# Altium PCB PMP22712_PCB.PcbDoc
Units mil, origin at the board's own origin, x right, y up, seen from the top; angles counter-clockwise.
Board outline 1309.06 x 1072.84 mil, 4 copper layers (Top Layer, Signal Layer 1, Signal Layer 2, Bottom Layer), stack 36.024 mil thick; 30 components, 23 nets, 81 pads, 8 vias.
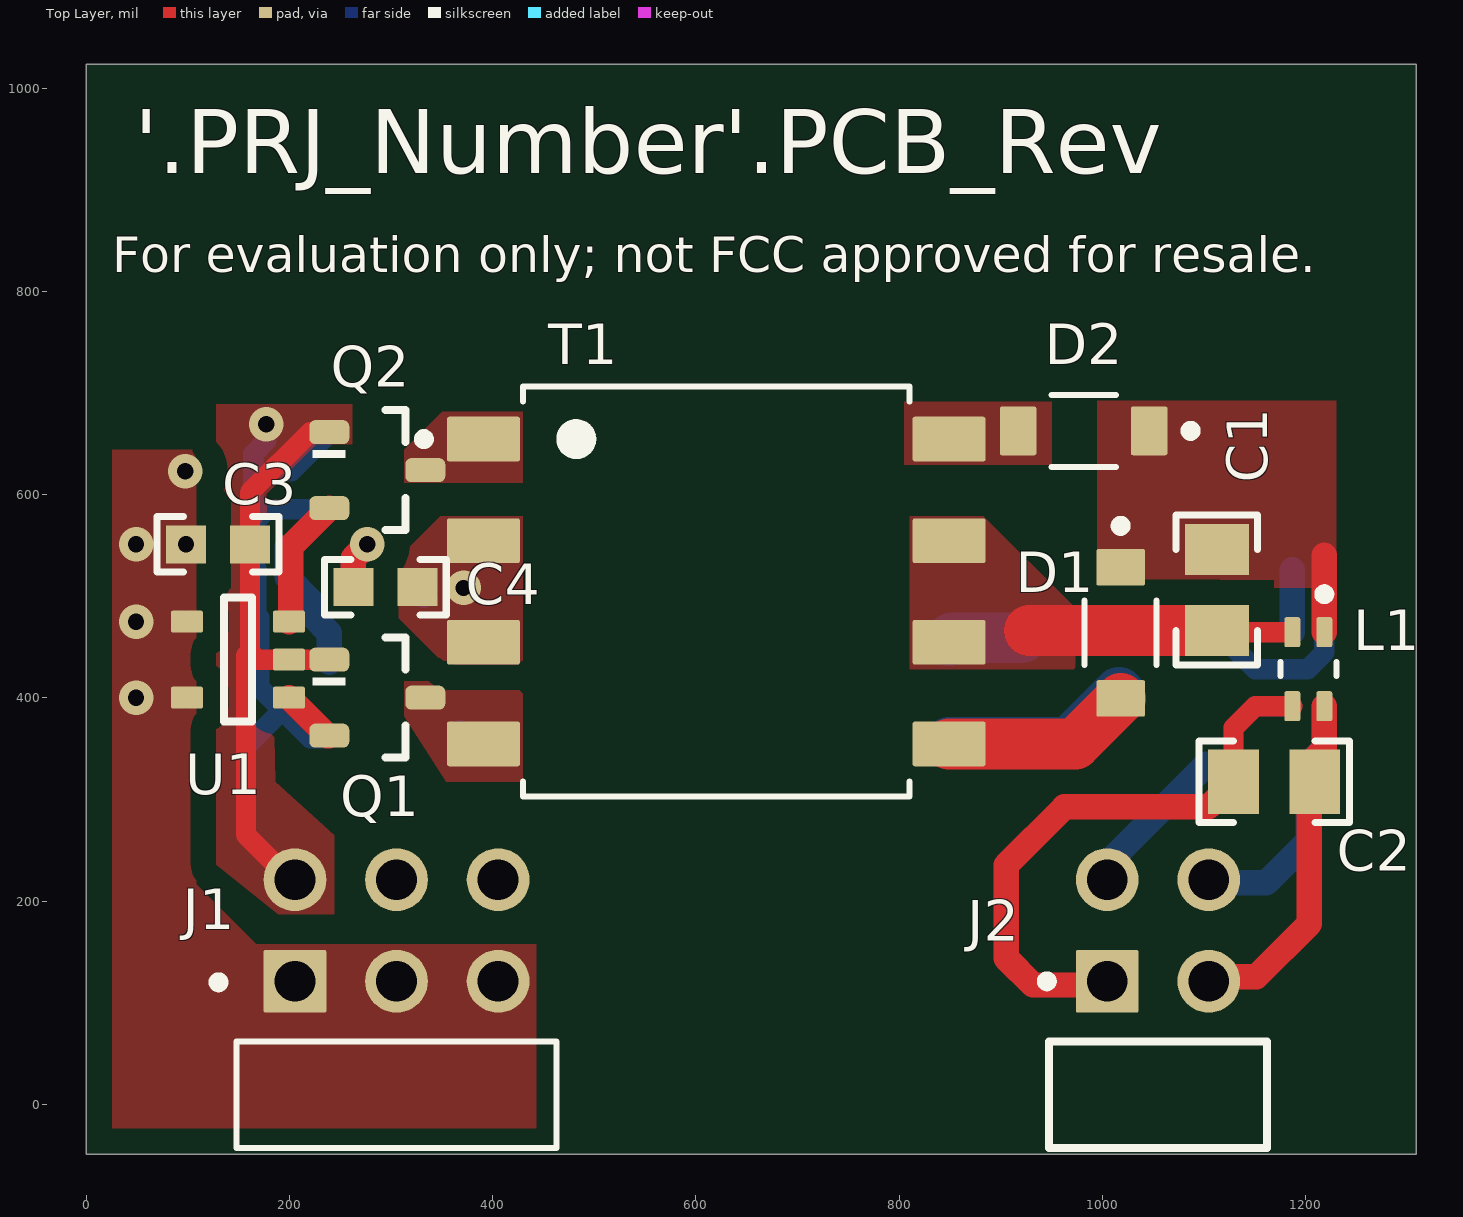
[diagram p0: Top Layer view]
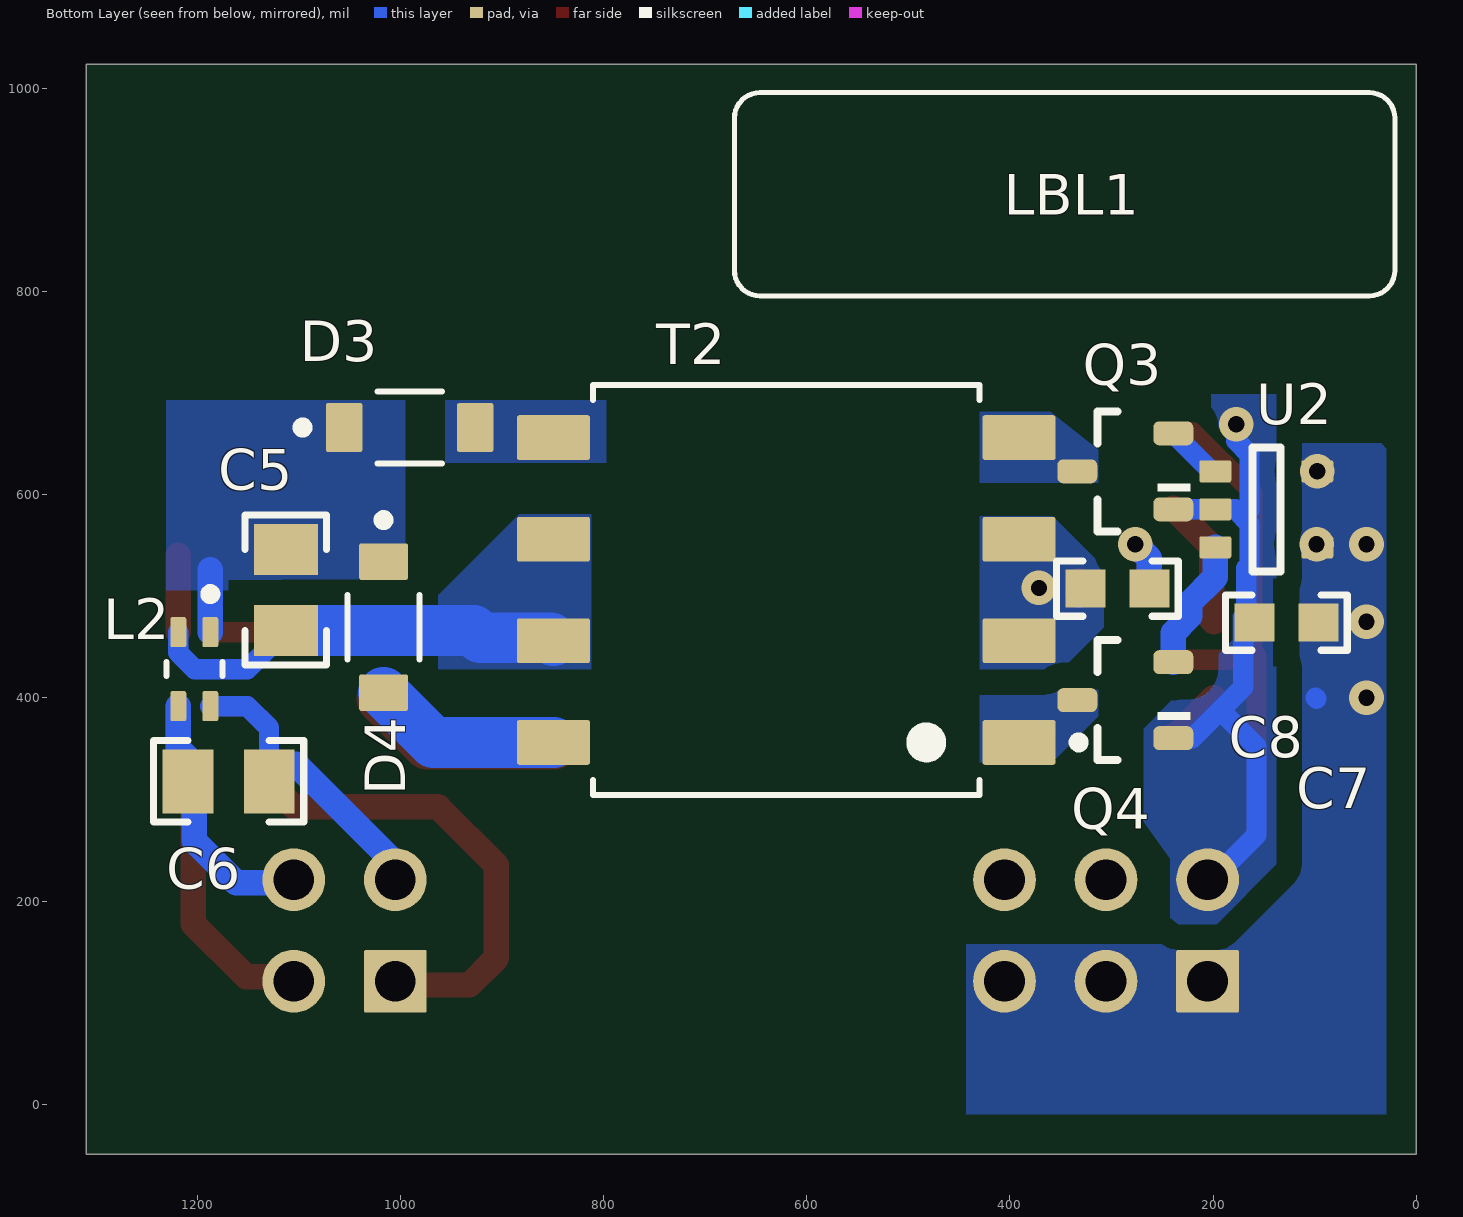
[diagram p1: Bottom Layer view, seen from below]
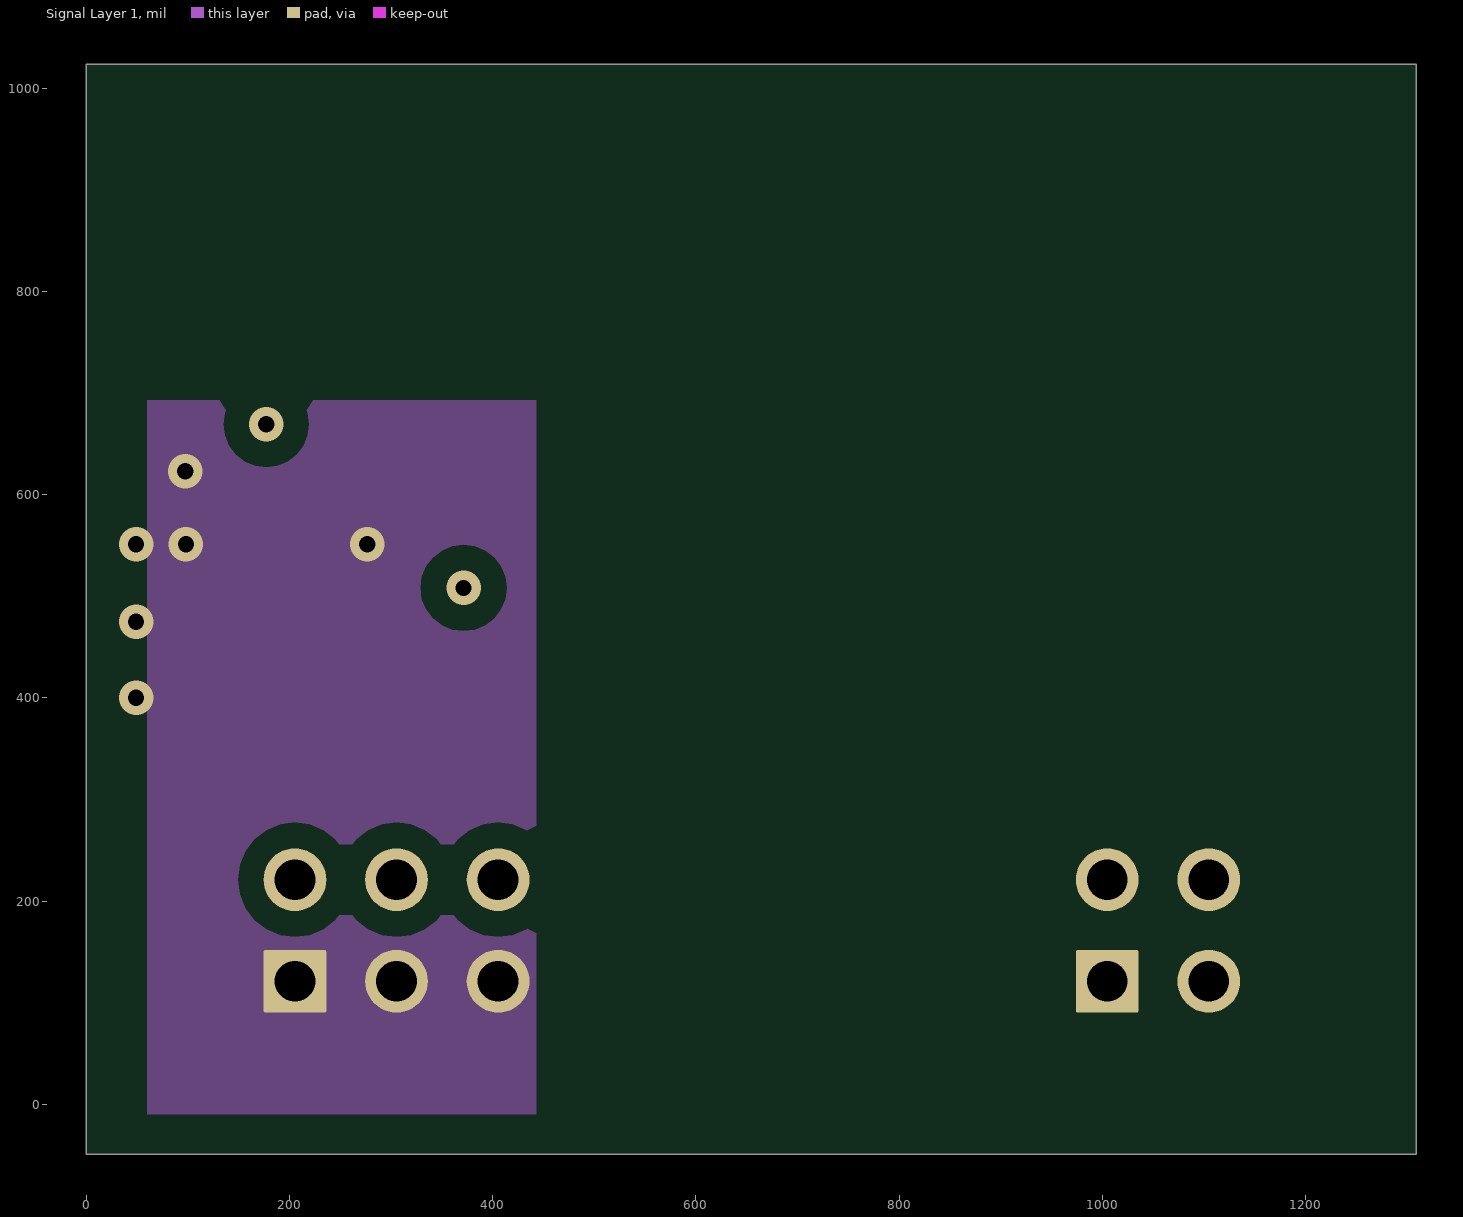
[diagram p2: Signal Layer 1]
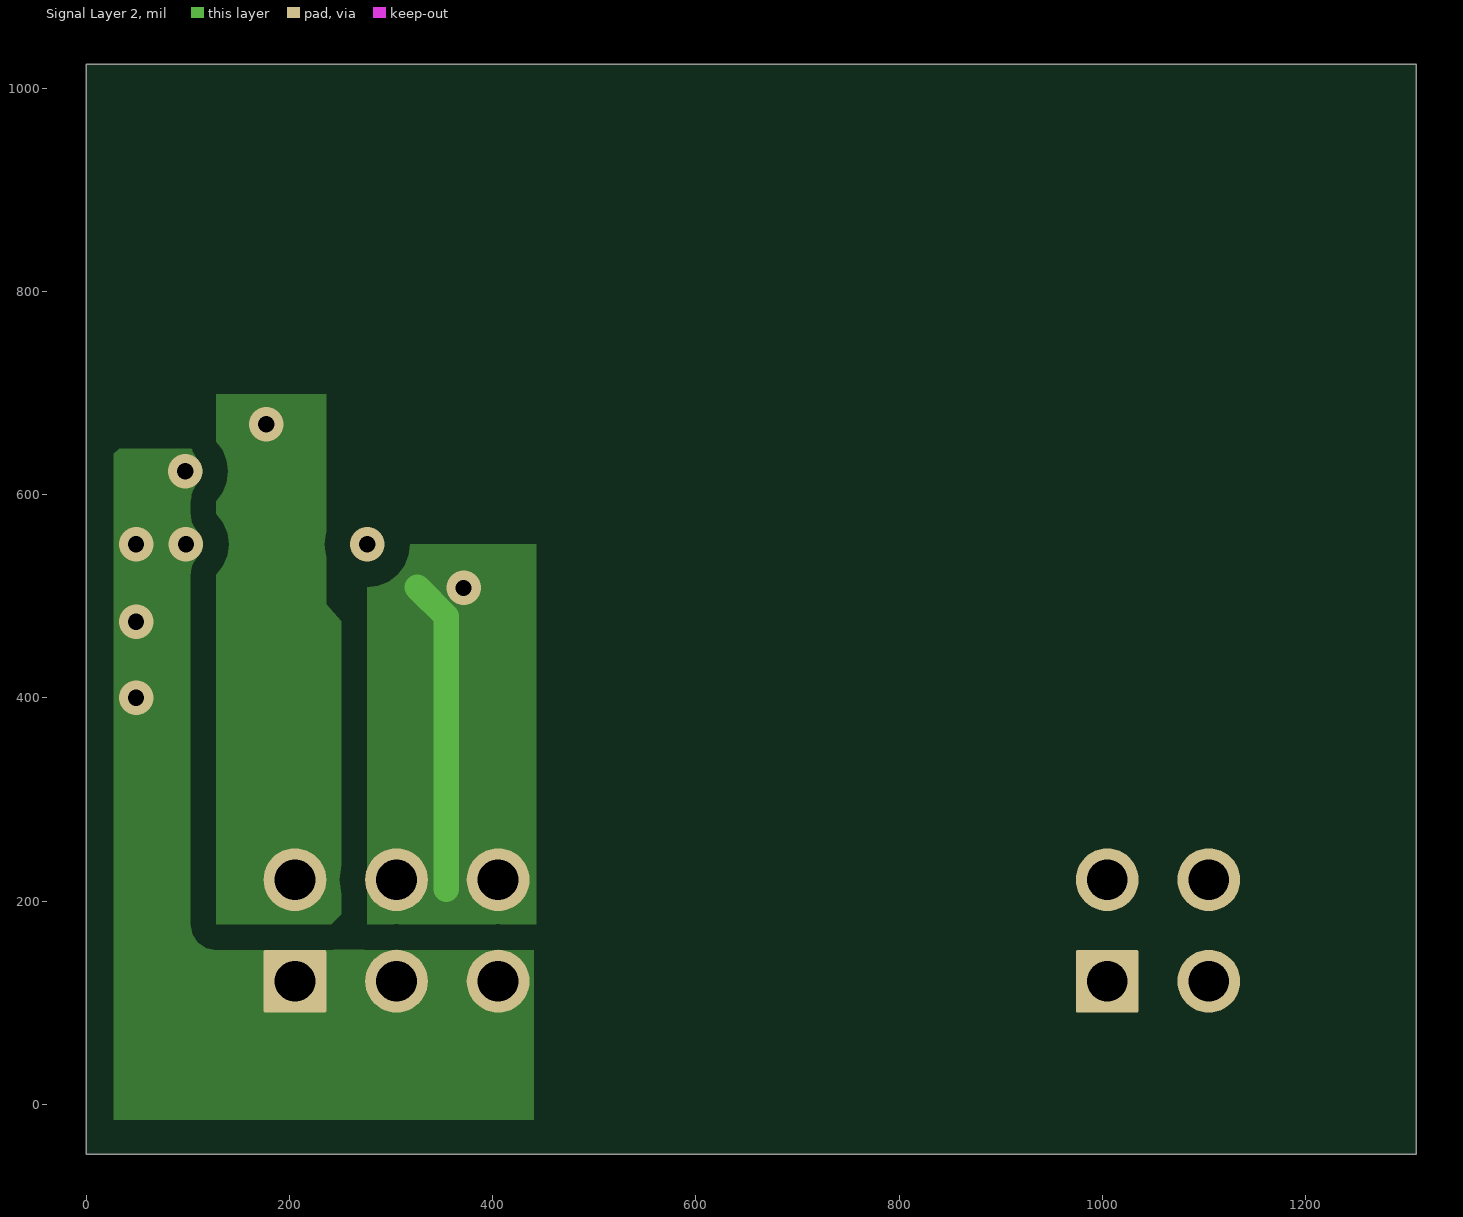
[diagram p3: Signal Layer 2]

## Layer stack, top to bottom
Top Solder: solder mask 0.4, Solder Resist, Dk 3.5
Top Layer: signal copper 2.7559
Dielectric 2: core 10, FR-4, Dk 4.2
Signal Layer 1: signal copper 2.7559
Dielectric1: prepreg 5, FR-4, Dk 4.2
Signal Layer 2: signal copper 2.7559
Dielectric 3: core 10, FR-4, Dk 4.2
Bottom Layer: signal copper 2.7559
Bottom Solder: solder mask 0.4, Solder Resist, Dk 3.5

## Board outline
0,-49.21 1309.06,-49.21 1309.05,1023.62 0,1023.62

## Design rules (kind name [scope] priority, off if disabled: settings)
AcuteAngle [All] p1: minimum=4.50000000000000E+0001 checktracksonly=FALSE
AssemblyTestPointUsage [All] p1: valid=2
BoardOutlineClearance BoardOutlineClearance_MountingHoles [OnCopper and InComponentClass('Mounting Holes')] p1: gap=39.37 ignorepadtopadclearanceinfootprint=FALSE
BoardOutlineClearance BoardOutlineClearance_Poly [OnCopper and IsPoly] p2: gap=25 ignorepadtopadclearanceinfootprint=FALSE
BoardOutlineClearance [OnCopper and Not InComponentClass('Logo') and not InComponentClass('FiducialMark') and not InRegion(1000,500,4000,800) and not InPoly] p3: gap=75 ignorepadtopadclearanceinfootprint=FALSE
Clearance Clearance_Keepouts [((IsTrack Or IsArc) And Not InPoly) And IsFree and IsKeepOut vs ((IsTrack Or IsArc) And Not InPoly) And IsFree and IsKeepOut] p1: gap=0 ignorepadtopadclearanceinfootprint=FALSE
Clearance Clearance_Poly [InPolygon] p2: gap=25 ignorepadtopadclearanceinfootprint=TRUE
Clearance Clearance_FiducialMark [IsKeepOut and InComponentClass('FiducialMark') vs IsPad and InComponentClass('FiducialMark')] p3: gap=0 ignorepadtopadclearanceinfootprint=FALSE
Clearance [All] p4: gap=7.87 ignorepadtopadclearanceinfootprint=TRUE
ComponentClearance ComponentClearance_MountingHoles_FiducialMarks [InComponentClass('Mounting Holes') vs InComponentClass('FiducialMark')] p1: gap=50 collisioncheckmode=3 verticalgap=10 showdistances=FALSE
ComponentClearance ComponentClearance_Shunt [InComponentClass('Header') vs InComponentClass('Shunt')] p2: gap=0 collisioncheckmode=3 verticalgap=0 showdistances=FALSE
ComponentClearance ComponentClearance_Logo [InComponentClass('Logo')] p3: gap=50 collisioncheckmode=3 verticalgap=10 showdistances=FALSE
ComponentClearance ComponentClearance_ScrewToNut [(HasFootprint('NY PMS 440 0025 PH')) vs (HasFootprint('Keystone_1902C'))] p4: gap=5 collisioncheckmode=3 verticalgap=10 showdistances=FALSE
ComponentClearance ComponentClearance_MountingHoles [InComponentClass('Mounting Holes')] p5: gap=250 collisioncheckmode=3 verticalgap=100000 showdistances=FALSE
ComponentClearance ComponentClearance_SmallPassives [HasFootprint('0201*') or HasFootprint('0402*') or HasFootprint('0508') or HasFootprint('0603*') or HasFootprint('0612') or HasFootprint('0805*') or HasFootprint('0815*') or HasFootprint('0830*') or HasFootprint('1206*') or HasFootprint('1210*') or HasFootprint('1808*') or HasFootprint('1812*') or HasFootprint('1825*') or HasFootprint('2010*') or HasFootprint('2220*') or HasFootprint('2225*') or HasFootprint('2512*') or HasFootprint('2728*') or HasFootprint('3518*') vs HasFootprint('0201*') or HasFootprint('0402*') or HasFootprint('0508') or HasFootprint('0603*') or HasFootprint('0612') or HasFootprint('0805*') or HasFootprint('0815*') or HasFootprint('0830*') or HasFootprint('1206*') or HasFootprint('1210*') or HasFootprint('1808*') or HasFootprint('1812*') or HasFootprint('1825*') or HasFootprint('2010*') or HasFootprint('2220*') or HasFootprint('2225*') or HasFootprint('2512*') or HasFootprint('2728*') or HasFootprint('3518*')] p6: gap=14.96 collisioncheckmode=3 verticalgap=10 showdistances=FALSE
ComponentClearance ComponentClearance_THtoSMT [IsThruComponent vs IsSMTComponent] p7: gap=40 collisioncheckmode=3 verticalgap=30 showdistances=FALSE
ComponentClearance ComponentClearance_THtoTH [IsThruComponent vs IsThruComponent] p8: gap=30 collisioncheckmode=3 verticalgap=30 showdistances=FALSE
ComponentClearance [All] p9: gap=30 collisioncheckmode=3 verticalgap=10 showdistances=FALSE
DiffPairsRouting [All] p1: maxlimit=100 minlimit=10 mostfreqgap=10 toplayer_minwidth=15 toplayer_maxwidth=15 toplayer_prefwidth=15 midlayer1_minwidth=15 midlayer1_maxwidth=15 midlayer1_prefwidth=15 midlayer2_minwidth=15 midlayer2_maxwidth=15 midlayer2_prefwidth=15 bottomlayer_minwidth=15 bottomlayer_maxwidth=15 bottomlayer_prefwidth=15 maxuncoupledlength=1000
FabricationTestPointUsage TestPointUsage [All] p1: valid=2 allowmultiple=FALSE
FabricationTestpoint Testpoint [All] p1: side=3 testpointundercomponent=TRUE minsize=40 maxsize=100 preferedsize=60 minholesize=0 maxholesize=40 preferedholesize=32 testpointgrid=1 allowsidetop=TRUE allowsidebottom=TRUE usegrid=TRUE gridtolerance=0.01
FanoutControl Fanout_LCC [IsLCC] p1: bgadir=Out bgaviamode=Centered fanoutstyle=Auto fanoutdirection=Alternating viagrid=1 // Fanout_LCC (Default Rule)
FanoutControl Fanout_BGA [IsBGA] p2: bgadir=Out bgaviamode=Centered fanoutstyle=Auto fanoutdirection=Alternating viagrid=1 // Fanout_BGA (Default Rule)
FanoutControl Fanout_Default [All] p4: bgadir=Out bgaviamode=Centered fanoutstyle=Auto fanoutdirection=Alternating viagrid=1 // Fanout_Default (Default Rule)
FanoutControl Fanout_Small [(CompPinCount < 5)] p5: bgadir=Out bgaviamode=Centered fanoutstyle=Auto fanoutdirection=OutThenIn viagrid=1 // Fanout_Small (Default Rule)
HoleSize [All] p1: absolutevalues=TRUE maxlimit=251 minlimit=7.87 maxpercent=80.000 minpercent=20.000
MinimumAnnularRing MinimumAnnularRing_ThermalPadVias [IsVia and InAnyComponent] p1: minimumring=5.91
MinimumAnnularRing [All] p2: minimumring=7.87
MinimumSolderMaskSliver MinimumSolderMaskSliver_Logo [InComponentClass('Logo') vs InComponentClass('Logo')] p1: minsoldermaskwidth=0.7
MinimumSolderMaskSliver [All] p2: minsoldermaskwidth=3.94
PlaneConnect [All] p1: planeconnectstyle=Direct reliefexpansion=10 reliefentries=4 reliefconductorwidth=10 reliefairgap=10
PolygonConnect [All] p1: connectstyle=Direct reliefconductorwidth=10 reliefentries=4 polygonreliefangle="90 Angle" airgapwidth=10
RoutingVias ThermalPadVias [IsVia and InAnyComponent] p1: holewidth=7.87 width=19.68 viastyle="Through Hole" minholewidth=7.87 minwidth=19.68 maxholewidth=12.99 maxwidth=23.62
RoutingVias [All] p2: holewidth=16 width=34 viastyle="Through Hole" minholewidth=7.87 minwidth=26 maxholewidth=40 maxwidth=65
SilkToBoardRegionClearance [Not ((IsComment or IsDesignator) And (Hide <> 'False')) and not InRegion(1000,500,4000,800)] p1:
SilkToSilkClearance SilkToSilkClearance_Pb-FreeLogo [(HasFootprint('Pb-Free_Overlay_Medium') OR HasFootprint('Pb-Free_Overlay_Small')) vs (HasFootprint('Pb-Free_Overlay_Medium') OR HasFootprint('Pb-Free_Overlay_Small'))] p1: silktosilkclearance=0
SilkToSilkClearance [All] p2: silktosilkclearance=3.94
SilkToSolderMaskClearance SilkToComponentPadClearance [(IsPad or IsFill or IsRegion) and InAnycomponent] p1: minsilkscreentomaskgap=5 clearancetoexposedcopper=TRUE
SilkToSolderMaskClearance "Silk to Solder Mask Opening" [All] p2: minsilkscreentomaskgap=3.94 clearancetoexposedcopper=FALSE
SolderMaskExpansion [All] p1: expansion=1.97 istentingtop=FALSE
UnRoutedNet [All] p1: checkbadconnections=TRUE
Width [All] p1: maxlimit=100 minlimit=6 preferedwidth=10 checkconnectedcopper=TRUE
14 further rules are at their usual default settings.

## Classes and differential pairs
net class VSWNET: H_T4 H_T5 H_T6 H_VOUT HS_GND ISO_12V_H
net class PGND: H_VOUT ISO_12V_L L_T4 L_T5 L_T6 LS_GND
net class INGND: 5V_PRI 12V_PRI H_D1 H_D2 H_FET_D1 H_FET_D2 L_D1 L_D2 L_FET_D1 L_FET_D2 PGND
component class PMP22712_Main: C1 C2 C3 C4 C5 C6 C7 C8 D1 D2 D3 D4 J1 J2 L1 L2 Q1 Q2 Q3 Q4 T1 T2 U1 U2
component class PMP22712_Hardware: LBL1 Logo3 ZZ1 ZZ2 ZZ3 ZZ4
component class AssemblyNote: ZZ1 ZZ2 ZZ3 ZZ4
component class Label: LBL1

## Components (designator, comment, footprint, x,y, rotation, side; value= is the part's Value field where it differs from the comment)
C1 "GRM21BR71E475KA73L" 0805_HV 1112.7,506.17 r270 top value=4.7uF
C2 "GRM21BR71E475KA73L" 0805_HV 1169.2,317.44 r180 top value=4.7uF
C3 "UMK107AB7105KA-T" 0603 129.62,551.17 r180 top value=1uF
C4 "UMK107AB7105KA-T" 0603 294.29,508.9 r180 top value=1uF
C5 "GRM21BR71E475KA73L" 0805_HV 1112.7,506.17 r270 bottom value=4.7uF
C6 "GRM21BR71E475KA73L" 0805_HV 1169.03,317.88 r0 bottom value=4.7uF
C7 "UMK107AB7105KA-T" 0603 127.95,474.09 r180 bottom value=1uF
C8 "UMK107AB7105KA-T" 0603 294.29,507.59 r180 bottom value=1uF
D1 "NRVB0540T1G" FP-NRVB0540T1G_SOD-123-MFG#1 1018.11,463.98 r270 top
D2 "NRVB0540T1G" FP-NRVB0540T1G_SOD-123-MFG#1 981.61,662.8 r180 top
D3 "NRVB0540T1G" FP-NRVB0540T1G_SOD-123-MFG#2 990.82,666.1 r180 bottom
D4 "NRVB0540T1G" FP-NRVB0540T1G_SOD-123-MFG#2 1016.42,469.68 r270 bottom
J1 "TSW-103-08-G-D-RA" FP-TSW-103-08-G-D-RA_HDR6-MFG 305.36,12.01 r0 top
J2 "TSW-102-08-G-D-RA" FP-TSW-102-08-G-D-RA_HDR4-MFG 1054.87,12.01 r0 top
L1 "ACM2012-900-2P-T001" FP-ACM2012-900-2P-T001_SMD4-MFG#1 1202.76,428.2 r270 top
L2 "ACM2012-900-2P-T001" FP-ACM2012-900-2P-T001_SMD4-MFG#2 1202.76,428.32 r270 bottom
LBL1 "THT-14-423-10" Label_650x200 346.08,895.67 r180 bottom
Logo3 "FCC disclaimer" FCC_disclaimer 2372.05,3120.08 r0 top
Q1 "ZXMN10A07FTA" SOT-23 286.42,400.23 r0 top value=100V
Q2 "ZXMN10A07FTA" SOT-23 286.42,624.14 r0 top value=100V
Q3 "ZXMN10A07FTA" SOT-23 286.42,622.93 r0 bottom value=100V
Q4 "ZXMN10A07FTA" SOT-23 286.42,397.77 r0 bottom value=100V
T1 "901-20113-V1-01" FP-901-20113-V1-01_SMT_XFRMR_9MM54_10MM26-MFG 620.08,504.69 r0 top
T2 "901-20113-V1-01" FP-901-20113-V1-01_SMT_XFRMR_9MM54_10MM26-MFG 620.08,506.17 r0 bottom
U1 "SN6501QDBVRQ1" DBV0005A_L 149.3,437.63 r180 top
U2 "SN6501QDBVRQ1" DBV0005A_L 147.64,585.53 r180 bottom
ZZ1 "This Assembly Note is for PCB labels only" AssemblyNoteLabel 185,3938 r0 top
ZZ2 "These assemblies are ESD sensitive, ESD precautions shall be observed." AssemblyNote 185,3829.11 r0 top
ZZ3 "These assemblies must be clean and free from flux and all contaminants. Use of no clean flux is not acceptable." AssemblyNote 185,3740.56 r0 top
ZZ4 "These assemblies must comply with workmanship standards IPC-A-610 Class 2, unless otherwise specified." AssemblyNote 185,3652 r0 top

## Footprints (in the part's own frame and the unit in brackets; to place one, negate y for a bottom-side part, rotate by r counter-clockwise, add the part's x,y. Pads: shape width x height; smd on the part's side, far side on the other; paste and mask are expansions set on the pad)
0603 [mm] "0603 from SM-752 data"
  rect 1x0.95 smd: 1(-0.8,0) 2(0.8,0)
  silkscreen extent -1.52,-0.69 1.52,0.69, body extent -0.87,-0.47 0.87,0.47, height 1
0805_HV [mil] "0805 with 30mil clearance between pads"
  rect 50x63 smd: 1(-40,0) 2(40,0)
  silkscreen extent -74,-40 74,40, body extent -43,-29 43,29, height 57
AssemblyNote [mil] "Assembly Note"
AssemblyNoteLabel [mil] "Assembly Note for PCB Labels"
DBV0005A_L [mm] "SOT23, 5-Leads, Body 2.9x1.6mm, Pitch 0.95mm, Lead Span 2.8mm, IPC High Density"
  rrect18% 0.8x0.55 smd: 1(-1.275,0.95) 2(-1.275,0) 3(-1.275,-0.95) 4(1.275,-0.95) 5(1.275,0.95)
  silkscreen extent -0.35,-1.55 0.35,1.55, body extent -1.42,-1.46 1.42,1.46, height 1.09
FCC_disclaimer [mil]
FP-901-20113-V1-01_SMT_XFRMR_9MM54_10MM26-MFG [mm]
  rrect9% 1.82x1.12 smd paste+0 mask+0: 1(-5.82,3.81) 2(-5.82,1.27) 3(-5.82,-1.27) 4(-5.82,-3.81) 5(5.82,-3.81) 6(5.82,-1.27) 7(5.82,1.27) 8(5.82,3.81)
  silkscreen extent -7.43,-5.13 4.83,5.13, body extent -6.83,-5.23 6.83,5.23, height 0.25
FP-ACM2012-900-2P-T001_SMD4-MFG#1 [mm]
  rrect25% 0.75x0.4 smd: 1(-0.925,0.4) 2(-0.925,-0.4) 3(0.925,-0.4) 4(0.925,0.4)
  silkscreen extent -2,-0.7 0.18,0.7, body extent -1.4,-0.8 1.4,0.8, height 0.25
FP-ACM2012-900-2P-T001_SMD4-MFG#2 [mm]
  rrect25% 0.75x0.4 smd paste+0 mask+0: 1(-0.925,0.4) 2(-0.925,-0.4) 3(0.925,-0.4) 4(0.925,0.4)
  silkscreen extent -2,-0.7 0.18,0.7, body extent -1,-0.6 1,0.6, height 1.3
FP-NRVB0540T1G_SOD-123-MFG#1 [mil]
  rrect11% 36x48 smd: 1(-64.5,0) 2(64.5,0)
  silkscreen extent -110,-35 32,35, body extent -86,-39 86,39, height 10
FP-NRVB0540T1G_SOD-123-MFG#2 [mil]
  rrect11% 36x48 smd paste+0 mask+0: 1(-64.5,0) 2(64.5,0)
  silkscreen extent -110,-35 32,35, body extent -72,-31 72,31, height 53
FP-TSW-102-08-G-D-RA_HDR4-MFG [mm]
  rrect6% 1.57x1.57 hole 1.02 paste-1000 mask+0: 1(-1.27,2.77)
  round 1.57 hole 1.02 paste-1000 mask+0: 2(-1.27,5.31) 3(1.27,2.77) 4(1.27,5.31)
  silkscreen extent -2.9,-1.4 2.73,2.89, body extent -2.83,-7.54 2.83,6.2, height 0.25
FP-TSW-103-08-G-D-RA_HDR6-MFG [mm]
  rrect6% 1.57x1.57 hole 1.02 paste-1000 mask+0: 1(-2.54,2.77)
  round 1.57 hole 1.02 paste-1000 mask+0: 2(-2.54,5.31) 3(0,2.77) 4(0,5.31) 5(2.54,2.77) 6(2.54,5.31)
  silkscreen extent -4.57,-1.4 4,2.87, body extent -4.1,-7.54 4.1,6.19, height 0.25
Label_650x200 [mil] "Thermal Transfer Label"
  round 1 on Mech14: 0(0,0)
  silkscreen extent -325,-100 325,100, body extent -325,-100 325,100, height 1
SOT-23 [mm] "SOT23, 3-Leads, Body 2.9x1.3mm, Pitch 0.95mm, Lead Span 2.5mm, IPC Medium Density"
  rrect50% 1x0.6 smd: 1(-1.2,0.95) 2(-1.2,-0.95) 3(1.2,0)
  silkscreen extent -1.63,-1.5 0.7,1.5, body extent -1.16,-1.45 1.21,1.45, height 1

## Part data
C1 C2 C5 C6: library part CMP-0008346-2, "CAP, CERM, 4.7 uF, 25 V, +/- 10%, X7R, 0805", Cap_Case=0805, Manufacturer=MuRata, Supplier Part Number 1=490-9962-1-ND, TempCo=X7R, Tolerance_%=10%, Value1=Unknown, Value2=25V, ValueDisplayed=4.7uF
C3 C4 C7 C8: library part CMP-0007508-5, "CAP, CERM, 1 uF, 50 V, +/- 10%, X7R, 0603", Cap_Case=0603, Manufacturer="Taiyo Yuden", Supplier Part Number 1=587-3247-1-ND, TempCo=X7R, Tolerance_%=10%, Value1=Unknown, Value2=50V, ValueDisplayed=1uF
D1 D2 D3 D4: library part CMP-0090564-1, "Diode Schottky 40V 500mA Surface Mount SOD-123", Digikey Part Number=NRVB0540T1GOSCT-ND, Forward Current=0.5A, Manufacturer="On Semiconductor", Max Surge Forward Current=5.5A, Mouser Part Number=863-NRVB0540T1G, Operating Temperature Range="-55°C to +150°C", Peak Reverse Current=20uA
J1: library part CMP-0090622-1, "Connector Header Through Hole, Right Angle 6 position 0.100\" (2.54mm)", Current_A=5.7A, Digikey Part Number=SAM1037-03-ND, Manufacturer=Samtec, Mouser Part Number=200-TSW10308GDRA, Operating Temperature Range="-55°C to +125°C", Voltage_V=550V
J2: library part CMP-0088304-1, "CONN HEADER R/A 4POS 2.54MM", Digikey Part Number=SAM1037-02-ND, Manufacturer=Samtec, Mouser Part Number=200-TSW10208GDRA, Operating Temperature Range="-55°C to +125°C"
L1 L2: library part CMP-0090488-1, "2 Line Common Mode Choke Surface Mount 90 Ohms @ 100MHz 400mA DCR 190mOhm", Digikey Part Number=445-15969-1-ND, Impedance At Frequency="90Ω @ 100MHz", Manufacturer=TDK, Mouser Part Number=810-ACM20129002PT001, Operating Temperature Range="-40°C to +105°C"
LBL1: library part CMP-0003625-1, "Thermal Transfer Printable Labels, 0.650\" W x 0.200\" H - 10,000 per roll", Manufacturer=Brady, Supplier Part Number 1=97C5133
Logo3: library part CMP-0074847-1, "FCC_disclaimer"
Q1 Q2 Q3 Q4: library part CMP-0001041-3, "MOSFET, N-CH, 100 V, 0.7 A, AEC-Q101, SOT-23", Alternate Manufacturer=None, Manufacturer="Diodes Inc.", Supplier Part Number 1=ZXMN10A07FCT-ND, Value2="2.9 nC"
T1 T2: library part CMP-0090597-1, "Automotive Transformer, 1:1, 80uH, 3500VAC, SMT, 9.54x10.26x5.38", Frequency_Fixed=300-620kHz, Manufacturer="Wurth Electronics", Operating Temperature Range="-40°C to +125°C", Voltage_Isolation_Vrms=3.5kV
U1 U2: library part CMP-0076093-1, "Automotive Low-Noise 350 mA, 410 kHz Transformer Driver, DBV0005A (SOT-23-5)", Alternate Manufacturer="Texas Instruments"
ZZ1: library part CMP-0003616-3
ZZ2: library part CMP-0077236-1
ZZ3: library part CMP-0077237-1
ZZ4: library part CMP-0077238-1

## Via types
v1: diameter 34, hole 16, Top Layer to Bottom Layer, 8 vias

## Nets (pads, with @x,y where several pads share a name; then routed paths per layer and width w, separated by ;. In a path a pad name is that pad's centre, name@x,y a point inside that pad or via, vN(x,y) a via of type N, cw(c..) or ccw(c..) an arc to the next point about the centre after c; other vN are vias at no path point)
5V_PRI: C3.1 C7.1 J1.2 Q1.1 Q2.1 Q3.1 Q4.1 U1.2 U2.2 | length 1230.9
  Top Layer w20: J1.2@204.43,217.81 157.29,264.96 157.29,441.68 161.11,445.5 ; Q1.1 U1.2 168.99,437.63 161.11,445.5 ; Q2.1 220.49,661.55 161.11,602.17 C3.1 161.11,445.5
  Bottom Layer w20: v1(177.17,669.29) 177.17,652.97 164.21,640.02 164.21,584.55 177.17,584.55 ; J1.2@204.43,217.81 157.29,264.96 157.29,352.5 192.71,387.92 ; Q4.1 220.27,360.36 192.71,387.92 ; Q3.1 U2.2 178.15,585.53 177.17,584.55 ; 177.17,584.55 164.21,571.59 164.21,531.04 167.46,527.79 167.46,481.86 170.28,479.05 170.28,410.36 192.71,387.92
12V_PRI: C4.1 C8.1 J1.4 J1.6 T1.2 T1.3 T2.2 T2.3 | length 397.3
  Top Layer w25: C4.1@331.99,515.1 C4.1 326.77,508.9 C4.1@332.97,502.7 ; T1.3@377.17,454.69 T1.3 ; T1.2@377.17,554.69 T1.2
  Signal Layer 2 w25: 325.79,508.9 354.43,480.25 354.43,211.68
  Bottom Layer w25: C8.1@329.89,508.9 325.79,508.9 332.26,502.42 C8.1@332.26,501.07 ; T2.2@377.17,456.17 T2.2 ; T2.3@377.17,556.17 T2.3
  other v1: 371.36,508.18
H_D1: Q1.2 U1.1 | length 55.2
  Top Layer w25: U1.1 236.9,362.83 Q1.2
H_D2: Q2.2 U1.3 | length 128.1
  Top Layer w25: U1.3 201.17,476.7 201.17,548.74 Q2.2
H_FET_D1: Q1.3 T1.4 | length 13.8
  Top Layer w25: T1.4@377.17,354.69 T1.4
H_FET_D2: Q2.3 T1.1 | length 13.8
  Top Layer w25: T1.1@377.17,654.69 T1.1
H_T4: D1.2 T1.5 | length 188.9
  Top Layer w25: T1.5 T1.5@850.26,355.74
  Top Layer w50: T1.5 973.32,354.69 D1.2
H_T5: C1.2 L1.2 T1.6 T1.7 | length 251.5
  Top Layer w20: C1.2 1114.25,464.62 1179,464.62
  Top Layer w50: 928.19,466.17 C1.2
H_T6: D2.2 T1.8
H_VOUT: C1.1 D1.1 D2.1 L1.1 | length 75.8
  Top Layer w25: L1.1 1218.5,540.38
HS_GND: C2.2 J2.1 L1.3 | length 578.5
  Top Layer w20: C2.2 1129.2,370.61 1150.37,391.78 L1.3
  Top Layer w25: J2.1@1003.94,117.39 931.83,117.39 905.51,143.72 905.51,235.5 962.73,292.72 1104.47,292.72 C2.2
ISO_12V_H: C2.1 J2.3 L1.4 | length 342.4
  Top Layer w25: J2.3@1103.94,125.66 1151.82,125.66 1203.74,177.58 1203.74,332.94 1202.76,333.93 1218.5,349.68 L1.4
ISO_12V_L: C6.1 J2.2 L2.4 | length 301.8
  Bottom Layer w20: C6.1@1139.76,334.5 1129.2,345.07 1129.2,370.61 1150.37,391.78 1186.88,391.78 L2.4
  Bottom Layer w25: J2.2@1003.94,217.97 1003.94,236.08 1102.36,334.5 C6.1@1139.76,334.5
L_D1: Q3.2 U2.1 | length 56.8
  Bottom Layer w20: U2.1 201.77,622.93 Q3.2
L_D2: Q4.2 U2.3 | length 130.1
  Bottom Layer w25: U2.3 197.83,518.69 222.74,493.78 222.74,480.45 239.17,464.01 Q4.2
L_FET_D1: Q3.3 T2.4 | length 13.8
  Bottom Layer w25: T2.4@377.17,656.17 T2.4
L_FET_D2: Q4.3 T2.1 | length 27.3
  Bottom Layer w25: T2.1@367.62,365.72 377.17,356.17 T2.1
L_T4: D3.2 T2.5
L_T5: C5.2 L2.2 T2.6 T2.7 | length 416
  Bottom Layer w20: C5.2 1150.54,428.32 1202.19,428.32 1218.5,444.64 L2.2
  Bottom Layer w50: T2.7 852.17,459.12 921.14,459.12 928.19,466.17 C5.2
L_T6: D4.2 T2.8 | length 187.5
  Bottom Layer w50: T2.8 967.41,356.17 D4.2
L_VOUT: C5.1 D3.1 D4.1 L2.1 | length 61.6
  Bottom Layer w25: 1186.88,526.27 1187.01,526.14 L2.1
LS_GND: C6.2 J2.4 L2.3 | length 255.1
  Bottom Layer w25: J2.4@1103.94,217.97 1161.42,217.97 1202.76,259.31 1202.76,334.5 1218.5,350.25 L2.3
PGND: C3.2 C4.2 C7.2 C8.2 J1.1 J1.3 J1.5 U1.4 U1.5 U2.4 U2.5 | length 100.1
  Top Layer w20: U1.4@98.12,476.01 U1.4
  Top Layer w25: C4.2 262.8,537.39 v1(276.57,551.17)
  Bottom Layer w20: 98.12,399.24 99.11,400.23
  Bottom Layer w25: C8.2 262.8,537.39 v1(276.57,551.17)
  other v1: 49,400.23 49,475.03 49,551.17 98.12,551.17 97.44,622.93
pads on no net: LBL1.0

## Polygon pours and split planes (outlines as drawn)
H_T5 on Top Layer "TOP_LAYER_H_T5_P030" (solid, pour order 30): 810.43,578.91 810.43,428.32 973.32,428.32 973.32,488.66 883.07,578.91
H_FET_D2 on Top Layer "TOP_LAYER_H_FET_D2_P029" (solid, pour order 29): 429.72,681.59 350.46,681.59 312.99,644.12 312.99,611.97 429.72,611.97
12V_PRI on Top Layer "TOP_LAYER_12V_PRI_P028" (solid, pour order 28): 429.72,578.91 348.56,578.91 305.12,535.47 305.12,480.84 357.76,428.2 429.72,428.2
H_T6 on Top Layer "TOP_LAYER_H_T6_P027" (solid, remove dead copper, pour order 27): 805.16,691.37 805.16,629.48 950.44,629.48 950.44,691.37
H_FET_D1 on Top Layer "TOP_LAYER_H_FET_D1_P025" (solid, pour order 25): 429.72,317.44 429.72,416.14 312.99,416.14 312.99,381.67 354.43,317.44
H_VOUT on Top Layer "TOP_LAYER_L_VOUT_P000" (solid, remove dead copper, pour order 0): 995.08,692.32 995.08,508.18 1230.31,508.18 1230.31,692.32
PGND on Top Layer "TOP_LAYER_PGND_P018" (solid, remove dead copper, pour order 18): 442.91,157.48 167.32,157.48 108.27,216.54 108.27,644.11 19.68,644.11 19.68,-29.53 442.91,-29.53
5V_PRI on Top Layer "TOP_LAYER_5V_PRI_P016" (solid, remove dead copper, pour order 16): 127.95,688.98 127.95,235.79 188.93,187.01 244.26,187.01 244.26,264.94 186.19,317.44 177.17,600.39 226.38,649.61 261.81,649.61 261.81,688.98
PGND on Signal Layer 2 "SIGNAL_LAYER_2_PGND_P032" (solid, remove dead copper, pour order 32): 440.6,152.3 184.69,152.3 115.8,221.2 115.8,645.31 32.3,645.31 27.21,640.22 27.21,-15.02 440.6,-15.02
5V_PRI on Signal Layer 2 "SIGNAL_LAYER_2_5V_PRI_P014" (solid, remove dead copper, pour order 14): 285.43,177.17 285.43,241.36 261.81,252.64 261.81,463.22 236.22,492.13 236.22,698.82 127.95,698.82 127.95,177.17
12V_PRI on Signal Layer 2 "SIGNAL_LAYER_2_12V_PRI_P006" (solid, remove dead copper, pour order 6): 276.57,551.17 442.91,551.17 442.91,177.17 276.57,177.17 276.57,338.71
L_FET_D2 on Bottom Layer "BOTTOM_LAYER_L_FET_D2_P031" (solid, pour order 31): 429.72,408.12 312.99,408.12 312.99,381.67 358.19,336.47 429.72,336.47
L_T5 on Bottom Layer "BOTTOM_LAYER_L_T5_P026" (solid, pour order 26): 962.73,428.32 812.14,428.32 812.14,580.62 883.07,580.62 962.73,500.96
12V_PRI on Bottom Layer "BOTTOM_LAYER_12V_PRI_P023" (solid, pour order 23): 429.72,428.2 348.56,428.2 305.12,471.64 305.12,526.27 357.76,578.91 429.72,578.91
L_FET_D1 on Bottom Layer "BOTTOM_LAYER_L_FET_D1_P024" (solid, pour order 24): 429.72,611.97 312.99,611.97 312.99,644.12 360.1,681.59 429.72,681.59
L_T4 on Bottom Layer "BOTTOM_LAYER_L_T4_P010" (solid, remove dead copper, pour order 10): 797.24,692.9 955.71,692.9 955.71,631.32 797.24,631.32
PGND on Bottom Layer "BOTTOM_LAYER_PGND_P022" (solid, remove dead copper, pour order 22): 442.91,157.48 187.01,157.48 118.11,226.38 118.11,650.49 34.62,650.49 29.53,645.4 29.53,-9.84 442.91,-9.84
5V_PRI on Bottom Layer "BOTTOM_LAYER_5V_PRI_P020" (solid, remove dead copper, pour order 20): 242.13,177.17 196.66,177.17 137.8,236.03 137.8,698.82 201.77,698.82 201.77,664.37 177.17,639.76 180.83,636.1 180.83,457.36 268.46,369.73 268.46,278.28 242.13,241.88
L_VOUT on Bottom Layer "BOTTOM_LAYER_H_VOUT_P012" (solid, remove dead copper, pour order 12): 995.08,692.9 995.08,506.17 1230.32,506.17 1230.32,692.9
PGND on Signal Layer 1 "SIGNAL_LAYER_1_PGND_P004" (solid, remove dead copper, pour order 4): 60.04,693.04 442.91,693.04 442.91,-9.84 60.04,-9.84

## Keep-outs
Keep-Out Layer:
  text ".Layer_Name" at 577,-858.49 h60

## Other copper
Top Layer:
  text ".Layer_Name" at 577,-858.49 h60
Bottom Layer:
  text ".Layer_Name" at 577,-858.49 h60

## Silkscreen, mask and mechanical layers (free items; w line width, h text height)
Top Overlay:
  text "'.PRJ_Number'.PCB_Rev" at 47.1,895.67 h108.27
  text ".Layer_Name" at 577,-858.49 h60
Bottom Overlay:
  text ".Layer_Name" at 577,-858.49 h60
Top Paste:
  text ".Layer_Name" at 577,-858.49 h60
Bottom Paste:
  text ".Layer_Name" at 577,-858.49 h60
Top Solder:
  text ".Layer_Name" at 577,-858.49 h60
  text ".Layer_Name" at 577,-858.49 h60
Bottom Solder:
  text ".Layer_Name" at 577,-858.49 h60
Drill Guide:
  text ".Layer_Name" at 577,-858.49 h60
M1 Board Outline:
  the board outline again, w10
  text ".Layer_Name" at 577,-858.49 h60
M2 Board Dimensions:
  rectangle: 0,-275 125,-150
  rectangle: 125,-400 500,-275
  lines w7: 0,-275 1000,-275 ; 125,-400 125,-150 ; 250,-400 250,-150 ; 500,-400 500,-150 ; 750,-400 750,-150 ; 0,-400 1000,-400 1000,-150 0,-150 0,-400
  text ".Layer_Name" at 577,-858.49 h60
M3 3D STEP Top:
  text ".Layer_Name" at 577,-858.49 h60
M4 3D STEP Bottom:
  text ".Layer_Name" at 577,-858.49 h60
M5 Assembly Top:
  lines w10: -292,-930.17 6308,-930.17 ; -292,-726.83 6310,-726.83 ; -292,-523.5 -292,-1133.5 3713,-1133.5 6310,-1133.5 6310,-523.5 -291.5,-523.5 -291.5,-1133.5 1284,-1133.5 ; 2173,-1133.5 2173,-523.5 ; 3440,-726.83 3440,-523.5 ; 4280,-726.83 4280,-523.5 ; 4902,-1140 4902,-937.17
  text "COMPONENTS MARKED 'DNP' SHOULD NOT BE POPULATED." at 1153.5,-318.5 h60
  text "ASSEMBLY VARIANT:" at 1153,-434 h60
  text ".VariantName" at 2189,-434 h60
  text "PCB VIEWED FROM TOP SIDE" at -228.5,-655.67 h60
  text "BOARD #:" at 2248,-655.67 h60
  text ".PRJ_Number" at 2793.5,-655.67 h60
  text "REV:" at 3638,-655.67 h60
  text ".PCB_Rev" at 3929.5,-655.67 h60
  text "SVN REV:" at 4476,-655.67 h60
  text ".VersionControl_RevNumber" at 4982,-655.67 h60
  text "TID #:" at 2248,-859 h60
  text ".TID" at 2793.5,-859 h60
  text "PLOT NAME =" at -228.5,-1064.34 h60
  text ".plot_File_Name" at 577,-1064.34 h60
  text "GENERATED    :" at 2250,-1064.34 h60
  text ".Print_Date" at 3119.5,-1064.34 h60
  text ".Print_Time" at 3848.5,-1064.34 h60
  text "TEXAS INSTRUMENTS" at 5113,-1064.34 h60
M6 Assembly Bottom:
  lines w10: -292.5,-727.33 6309.5,-727.33 ; -290.5,-930.67 6309.5,-930.67 ; 1115.5,-1140.5 1115.5,-937.67 ; 1737.5,-727.33 1737.5,-524 ; 2577.5,-727.33 2577.5,-524 ; 3844.5,-1134 3844.5,-524 ; 4733.5,-1134 6309,-1134 6309,-524 -292.5,-524 -292.5,-1134 2304.5,-1134 6309.5,-1134 6309.5,-524
  text "COMPONENTS MARKED 'DNP' SHOULD NOT BE POPULATED." at 6102,-318 h60
  text ".VariantName" at 5058,-434 h60
  text "ASSEMBLY VARIANT:" at 6097,-434 h60
  text ".VersionControl_RevNumber" at 1035.5,-656.17 h60
  text "SVN REV:" at 1541.5,-656.17 h60
  text ".PCB_Rev" at 2088,-656.17 h60
  text "REV:" at 2379.5,-656.17 h60
  text ".PRJ_Number" at 3224,-656.17 h60
  text "BOARD #:" at 3769.5,-656.17 h60
  text "PCB VIEWED FROM BOTTOM SIDE" at 6246,-656.17 h60
  text ".TID" at 3224,-859.5 h60
  text "TID #:" at 3769.5,-859.5 h60
  text "TEXAS INSTRUMENTS" at 904.5,-1064.84 h60
  text ".Print_Time" at 2169,-1064.84 h60
  text ".Print_Date" at 2898,-1064.84 h60
  text "GENERATED    :" at 3767.5,-1064.84 h60
  text ".plot_File_Name" at 5440.5,-1064.84 h60
  text "PLOT NAME =" at 6246,-1064.84 h60
M9 Title Sheet:
  drawing of 57 lines, arcs and shapes, not listed
  text "1" at 739.84,8036.5 h70
  text "2" at 3235.5,8036.5 h70
  text "3" at 5724.84,8036.5 h70
  text "4" at 8231.51,8036.5 h70
  text "5" at 10730.5,8036.5 h70
  text "6" at 13235.5,8036.5 h70
  text "A" at -416.5,6893.5 h70
  text "A" at 14383.5,6893.5 h70
  text "B" at -416.5,4513.5 h70
  text "B" at 14383.5,4513.5 h70
  text "C" at -416.5,2138.5 h70
  text "C" at 14383.5,2138.5 h70
  text "PROJECT TITLE:" at 11343.5,277.5 h45
  text ".PRJ_Title" at 11393.5,144.17 h70
  text "DESIGNED FOR:" at 11343.5,-23.5 h45
  text ".PRJ_Customer" at 11393.5,-163.5 h70
  text "D" at -416.5,-231.5 h70
  text "D" at 14383.5,-231.5 h70
  text "FILE NAME:" at 11343.5,-323.5 h45
  text ".PCB_File_Name_No_Path" at 11393.5,-443.5 h70
  text "Texas Instruments (TI) and/or its licensors do not warrant the accuracy or completeness of this specification" at 6374,-605.34 h45
  text "ENGINEER:" at 11343.5,-613.5 h45
  text "LAYOUT BY:" at 12848.5,-613.5 h45
  text "or any information contained therein. TI and/or its licensors do not warrant that this design will meet" at 6329.01,-718 h45
  text ".PRJ_Engineer" at 11393.5,-768.49 h70
  text ".PCB_Layout" at 12899,-768.49 h70
  text "the specifications, will be suitable for your application or fit for any particular purpose, or will operate in" at 6329.01,-830.67 h45
  text ".Layer_Name" at 577,-858.49 h60
  text "ALTIUM DESIGNER VERSION:" at 12848.5,-923.5 h45
  text "an implementation. TI and/or its licensors do not warrant that the design is production worthy. You should" at 6329.01,-943.33 h45
  text "completely validate and test your design implementation to confirm the system functionality for your application." at 6374,-1056 h45
  text ".print_Scale" at 11393.5,-1056.83 h70
  text ".Application_BuildNumber" at 12899,-1056.83 h70
  text "1" at 739.84,-1263.5 h70
  text "2" at 3235.5,-1263.5 h70
  text "3" at 5724.84,-1263.5 h70
  text "4" at 8231.51,-1263.5 h70
  text "5" at 10730.5,-1263.5 h70
  text "6" at 13235.5,-1263.5 h70
M10 Fab Notes:
  drawing of 189 lines, arcs and shapes, not listed
  text "DESIGN INFORMATION" at 12382.02,6356.17 h60
  text "MIN. TRACK WIDTH:" at 11737.46,6224.05 h60
  text "8" at 12833.7,6224.05 h60
  text "MIL" at 12988.46,6224.05 h60
  text "MIN. CLEARANCE:" at 11737.46,6099.92 h60
  text "0.2" at 12773.7,6099.93 h60
  text "mm" at 12988.46,6099.92 h60
  text "MIN. VIA PAD SIZE:" at 11737.46,5975.8 h60
  text "24" at 12803.71,5975.8 h60
  text "MIL" at 12988.46,5975.8 h60
  text "0.05mm (2MIL)" at 12432.46,5845.9 h60
  text "MINIMUM ANNULAR RING" at 11408.23,5837.67 h60
  text "EXTERNAL" at 13140.46,5837.67 h60
  text "PER" at 11608.23,5727.55 h60
  text "IPC-D-275 CLASS 2 LEVEL C" at 11828.23,5727.54 h60
  text "MIL, HOLES" at 13316.46,5627.07 h60
  text "+/-" at 12924,5618.48 h60
  text "+/-" at 13778,5618.48 h60
  text "REGISTRATION TOLERANCES:" at 11408.23,5617.42 h60
  text "METAL" at 12608,5617.42 h60
  text "5" at 13184.2,5617.42 h60
  text "3" at 14017.2,5617.42 h60
  text "MIL" at 14133.46,5617.42 h60
  text "HOLE SIZE TOLERANCE (UNLESS OTHERWISE SPECIFIED):" at 11408.23,5519.1 h60
  text "+/-" at 13778,5516.23 h60
  text "3" at 14017.2,5515.17 h60
  text "MIL" at 14133.46,5515.17 h60
  text "MATERIAL:" at 11333.46,5377.52 h60
  text "FR-4 High Tg" at 12319.9,5249 h60
  text "X" at 12175.46,5241.01 h60
  text "FR-408" at 11754.46,5236.49 h60
  text "OTHER" at 13242.46,5236.49 h60
  text "62 MIL (1.6mm) +/-10%" at 12074.56,5093.46 h60
  text "X" at 11954.46,5091.01 h60
  text "THICKNESS:" at 11408.23,5085.24 h60
  text "OTHER" at 13359.46,5085.24 h60
  text "TOLERANCE:" at 11408.23,4946.92 h60
  text "X" at 12256.46,4946.92 h60
  text "ANSI IPC-6012 TYPE 3 CLASS 2" at 12434.48,4946.92 h60
  text "OTHER +/-" at 12434.46,4802.73 h60
  text "BOW & TWIST:" at 11408.23,4657.54 h60
  text "X" at 12256.46,4657.54 h60
  text "ANSI IPC-6012 TYPE 3 CLASS 2" at 12434.48,4657.54 h60
  text "OTHER +/-" at 12434.46,4510.85 h60
  text "DRILLING:" at 11333.46,4380.23 h60
  text "NC_DRILL FILES" at 13094.46,4275.04 h60
  text "REFERENCE:" at 11408.23,4271.1 h60
  text "X" at 12065.46,4271.01 h60
  text "AS SHOWN" at 12243.46,4271.1 h60
  text "X" at 12966.46,4271.1 h60
  text "OTHER" at 13392.46,4128.85 h60
  text "PTH COPPER THICKNESS:" at 11407.91,4125.32 h60
  text "X" at 12547.14,4125.32 h60
  text "20-30 um" at 12675.14,4125.32 h60
  text "BOARD FINISH:" at 11333.46,3977.73 h60
  text "SILKSCREEN:" at 11488.68,3867.6 h60
  text "X" at 12446.46,3867.6 h60
  text "TOP" at 12563.46,3867.6 h60
  text "X" at 12956.46,3867.6 h60
  text "BOTTOM" at 13074.46,3867.6 h60
  text "SILKSCREEN COLOR:" at 11488.68,3712.41 h60
  text "X" at 12445.46,3712.41 h60
  text "WHITE" at 12563.46,3712.41 h60
  text "OTHER" at 13074.46,3712.41 h60
  text "X" at 12576.46,3568.96 h60
  text "GREEN" at 12694.46,3568.96 h60
  text "OTHER" at 13312.46,3568.96 h60
  text "SOLDER RESIST COLOR:" at 11488.68,3562.1 h60
  text "X" at 12576.46,3414.71 h60
  text "MATTE" at 12694.46,3414.71 h60
  text "SEMI-GLOSS" at 13312,3414.07 h60
  text "IMMERSION GOLD (ENIG)" at 12394.46,3241.94 h60
  text "ENEPIG" at 13732,3234.72 h60
  text "SURFACE FINISH:" at 11333.46,3233.72 h60
  text "X" at 12216.46,3233.72 h60
  text "IMM. TIN/SILVER OR EQUIV" at 11663,3096.4 h60
  text "OTHER" at 13094.46,3092.47 h60
  text "ARRAY/PANEL:" at 11333.46,2937.09 h60
  text "CUT AND TRIM PER M1 BOARD OUTLINE" at 12394.46,2928.87 h60
  text "N.C. ROUTE" at 12394.46,2792.9 h60
  text "X" at 13082.46,2792.9 h60
  text "V. SCORE" at 13260.46,2792.9 h60
  text "CERTIFICATION:" at 11333.46,2663.77 h60
  text "MATERIALS AND WORKMANSHIP FOR ALL PCBS" at 12058.46,2663.77 h60
  text "TO MEET OR EXCEED THE REQUIREMENTS OF:" at 12058.46,2569.71 h60
  text "X" at 11695.97,2441.08 h60
  text "ANSI IPC-A-600F CLASS ->" at 11823.96,2441.08 h60
  text "X" at 13471.97,2441.08 h60
  text "2" at 13581.96,2441.08 h60
  text "1" at 13266.96,2439.58 h60
  text "3" at 13935.96,2439.58 h60
  text "X" at 12507.97,2293.39 h60
  text "RoHS" at 12635.96,2293.39 h60
  text "OTHER" at 13280.36,2293.39 h60
  text "PER ORDER" at 13677.42,2293.39 h60
  text "ALL BOARDS MUST MEET OR EXCEED UL94-V0 REQUIREMENTS." at 11361,2139.57 h60
  text "PCB MUST BEAR THE UL94V-0 UL REGISTERED MATERIAL ID NUMBER" at 11361,2023.5 h60
  text "ADDITIONAL REQUIREMENTS:" at 11333.46,1854.08 h60
  text "MICROSECTION:" at 11408.23,1746.95 h60
  text "YES" at 12313.96,1746.95 h60
  text "REQUIRED" at 13175.46,1602.62 h60
  text "BARE BOARD ELEC. TEST:" at 11408.23,1599.76 h60
  text "NONE" at 12713.96,1599.76 h60
  text "X" at 13057.46,1599.76 h60
  text "PER ORDER" at 13767.46,1599.76 h60
  text "XX MIL VIAS REQUIRE NON-CONDUCTIVE FILL AND PLANARIZE" at 11576.38,1394.82 h59
  text "XX MIL VIAS REQUIRE CONDUCTIVE FILL AND PLANARIZE" at 11584.38,1290.84 h60
  text "OUTER XX MIL TRACES REQUIRE 50 OHM SINGLE-ENDED IMPEDANCE" at 11583.39,1127.46 h58
  text "LAYER 2 & 3 (INNER LAYERS) XX MIL WIDE, XX MIL SPACE / TRACES REQUIRE 100 OHM DIFFERENTIAL IMPEDANCE" at 11575.39,891.74 h60
  text ".Layer_Name" at 577,-858.49 h60
M11 Gerber Information:
  lines w10: -292,-930.17 6308,-930.17 ; -292,-726.83 6310,-726.83 ; -292,-523.5 -292,-1133.5 3713,-1133.5 6310,-1133.5 6310,-523.5 -291.5,-523.5 -291.5,-1133.5 1284,-1133.5 ; 2173,-1133.5 2173,-523.5 ; 3440,-726.83 3440,-523.5 ; 4280,-726.83 4280,-523.5 ; 4902,-1140 4902,-937.17
  text "ALL ARTWORK VIEWED FROM TOP SIDE" at -228.5,-655.67 h60
  text "BOARD #:" at 2248,-655.67 h60
  text ".PRJ_Number" at 2793.5,-655.67 h60
  text "REV:" at 3638,-655.67 h60
  text ".PCB_Rev" at 3929.5,-655.67 h60
  text "SVN REV:" at 4476,-655.67 h60
  text ".VersionControl_RevNumber" at 4982,-655.67 h60
  text "LAYER NAME =" at -228.5,-858.49 h60
  text "TID #:" at 2248,-859 h60
  text ".TID" at 2793.5,-859 h60
  text "PLOT NAME =" at -228.5,-1064.34 h60
  text ".plot_File_Name" at 577,-1064.34 h60
  text "GENERATED    :" at 2250,-1064.34 h60
  text ".Print_Date" at 3119.5,-1064.34 h60
  text ".Print_Time" at 3848.5,-1064.34 h60
  text "TEXAS INSTRUMENTS" at 5113,-1064.34 h60
M12 Stackup:
  drawing of 295 lines, arcs and shapes, not listed
  text "Layer" at 9821.59,7604.94 h60
  text "Name" at 10231.51,7604.94 h60
  text "Material" at 11171.25,7604.94 h60
  text "Thickness" at 12031.02,7604.94 h60
  text "Constant" at 12680.85,7604.94 h60
  text "Board Layer Stack" at 13250.71,7604.94 h60
  text "Top Overlay" at 10231.51,7484.94 h60
  text "Top Solder" at 10231.51,7364.94 h60
  text "Solder Resist" at 11171.25,7364.94 h60
  text "0.40mil" at 12031.02,7364.94 h60
  text "3.5" at 12680.85,7364.94 h60
  text "1" at 9821.59,7244.94 h60
  text "Top Layer" at 10231.51,7244.94 h60
  text "Copper" at 11171.25,7244.94 h60
  text "2.76mil" at 12031.02,7244.94 h60
  text "Dielectric 2" at 10231.51,7124.94 h60
  text "FR-4" at 11171.25,7124.94 h60
  text "10.00mil" at 12031.02,7124.94 h60
  text "4.2" at 12680.85,7124.94 h60
  text "2" at 9821.59,7004.94 h60
  text "Signal Layer 1" at 10231.51,7004.94 h60
  text "Copper" at 11171.25,7004.94 h60
  text "2.76mil" at 12031.02,7004.94 h60
  text "Dielectric1" at 10231.51,6884.94 h60
  text "FR-4" at 11171.25,6884.94 h60
  text "5.00mil" at 12031.02,6884.94 h60
  text "4.2" at 12680.85,6884.94 h60
  text "3" at 9821.59,6764.94 h60
  text "Signal Layer 2" at 10231.51,6764.94 h60
  text "Copper" at 11171.25,6764.94 h60
  text "2.76mil" at 12031.02,6764.94 h60
  text "Dielectric 3" at 10231.51,6644.94 h60
  text "FR-4" at 11171.25,6644.94 h60
  text "10.00mil" at 12031.02,6644.94 h60
  text "4.2" at 12680.85,6644.94 h60
  text "4" at 9821.59,6524.94 h60
  text "Bottom Layer" at 10231.51,6524.94 h60
  text "Copper" at 11171.25,6524.94 h60
  text "2.76mil" at 12031.02,6524.94 h60
  text "Bottom Solder" at 10231.51,6404.94 h60
  text "Solder Resist" at 11171.25,6404.94 h60
  text "0.40mil" at 12031.02,6404.94 h60
  text "3.5" at 12680.85,6404.94 h60
  text "Bottom Overlay" at 10231.51,6284.94 h60
  text ".Layer_Name" at 577,-858.49 h60
M13 Component Bodies Top:
  text ".Layer_Name" at 577,-858.49 h60
M14 Component Bodies Bottom:
  text ".Layer_Name" at 577,-858.49 h60
M15 Courtyards Top:
  text ".Layer_Name" at 577,-858.49 h60
M16 Courtyards Bottom:
  text ".Layer_Name" at 577,-858.49 h60
Drill Drawing:
  circle w10: c5363.72,3362.28 r27.63
  lines w10: 5336.09,3210.34 5391.34,3210.34 5391.34,3265.59 5336.09,3265.59 5336.09,3210.34
  lines w12: 5286,3173.04 8517.49,3173.04 ; 5286,3421.68 8517.49,3421.68 ; 5623.86,3048.72 5623.86,3546 ; 5955.86,3048.72 5955.86,3546 ; 6592.43,3048.72 6592.43,3546 ; 6851.57,3048.72 6851.57,3546 ; 7226.72,3048.72 7226.72,3546 ; 7951.05,3048.72 7951.05,3546 ; 5286,3048.72 8517.49,3048.72 8517.49,3546 5286,3546 5286,3048.72
  text "Symbol" at 5360.59,3458.98 h72
  text "Quantity" at 5661.16,3458.98 h72
  text "Finished Hole Size" at 5993.16,3458.98 h72
  text "Plated" at 6629.72,3458.98 h72
  text "Hole Type" at 6888.86,3458.98 h72
  text "Drill Layer Pair" at 7264.02,3458.98 h72
  text "Hole Tolerance" at 7988.35,3458.98 h72
  text "8" at 5661.16,3334.66 h60
  text "16.00mil (0.406mm)" at 5993.16,3334.66 h60
  text "PTH" at 6629.72,3334.66 h60
  text "Round" at 6888.86,3334.66 h60
  text "Top Layer - Bottom Layer" at 7264.02,3334.66 h60
  text "10" at 5661.16,3210.34 h60
  text "40.16mil (1.020mm)" at 5993.16,3210.34 h60
  text "PTH" at 6629.72,3210.34 h60
  text "Round" at 6888.86,3210.34 h60
  text "Top Layer - Bottom Layer" at 7264.02,3210.34 h60
  text "18 Total" at 5661.16,3086.02 h60
  text ".Layer_Name" at 577,-858.49 h60
M17 Embedded Cavity:
  text ".Layer_Name" at 577,-858.49 h60
M18 Embedded Assembly:
  text ".Layer_Name" at 577,-858.49 h60
M19 Embedded Keepout:
  text ".Layer_Name" at 577,-858.49 h60

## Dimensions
0,-400 to 1000,-400 on M2 Board Dimensions
0,0 to 0,1023.62 on M2 Board Dimensions
0,0 to 1309.06,-49.21 on M2 Board Dimensions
